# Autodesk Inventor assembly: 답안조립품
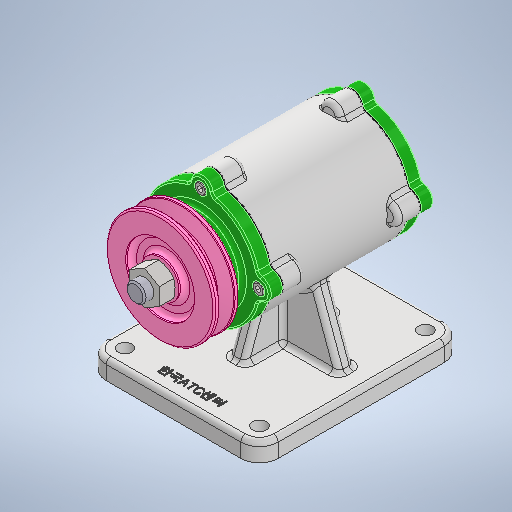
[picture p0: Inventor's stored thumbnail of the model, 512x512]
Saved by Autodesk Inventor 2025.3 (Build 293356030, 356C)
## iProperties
Created: 2025-08
Part Number: 답안조립품
Document SubType Name: Assembly
Designer: user
Author: user
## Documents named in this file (12)
- C:\Users\user\Desktop\750806V1012\답안조립품.iam
- C:\Users\user\Desktop\750806V1012\본체.ipt
- C:\Users\user\Desktop\750806V1012\V-벨트풀리\V-벨트풀리.ipt
- C:\Users\user\Desktop\750806V1012\개스킷\개스킷.ipt
- C:\Users\user\Desktop\750806V1012\너트 M12 x 1.25\너트 M12 x 1.25.ipt
- C:\Users\user\Desktop\750806V1012\뒤커버\뒤커버.ipt
- C:\Users\user\Desktop\750806V1012\베어링 6204\베어링 6204.ipt
- C:\Users\user\Desktop\750806V1012\볼트 M4 x 12\볼트 M4 x 12.ipt
- C:\Users\user\Desktop\750806V1012\앞커버\앞커버.ipt
- C:\Users\user\Desktop\750806V1012\오일 실\오일 실.ipt
- C:\Users\user\Desktop\750806V1012\축\축.ipt
- C:\Users\user\Desktop\750806V1012\키 4 x 4\키 4 x 4.ipt
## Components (3 placed, 2 different names)
1. V-벨트풀리:1
2. 개스킷:1
3. 개스킷:2
